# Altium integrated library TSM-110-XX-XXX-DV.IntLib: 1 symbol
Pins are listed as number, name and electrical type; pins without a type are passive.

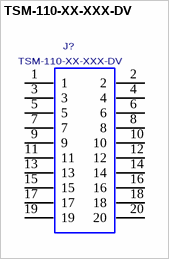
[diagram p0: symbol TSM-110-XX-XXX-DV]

## TSM-110-XX-XXX-DV
designator J?
DOUBLE ROW SURFACE MOUNT TERMINAL STRIP; MANUFACTURER: SAMTEC
footprint TSM-110-XX-XXX-DV
pins: 1, 2, 3, 4, 5, 6, 7, 8, 9, 10, 11, 12, 13, 14, 15, 16, 17, 18, 19, 20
